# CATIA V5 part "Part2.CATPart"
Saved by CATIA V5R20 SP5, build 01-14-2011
Part number: Part2
Bounding box of the stored display mesh (mm): x -30 to 30, y -75 to 75, z -75 to 75
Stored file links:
  E:\180122237\shuichi\Part2.CATPart
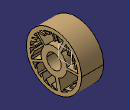
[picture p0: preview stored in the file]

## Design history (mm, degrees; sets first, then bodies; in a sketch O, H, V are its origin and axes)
Body1 (main body)
  Sketch1 on yz-plane, origin (0, 0, 0), H (0, 1, 0), V (0, 0, 1)
    circle A1 centre (0, 0) radius 20
    point P1 (20, 0)
    arc A2 centre (0, 0) radius 35 from (12.1786, -32.8128) to (34.8547, -3.1854) ccw
    arc A3 centre (0, 0) radius 65 from (20, -61.8466) to (38.5836, -52.3097) ccw
    circle A4 centre (0, 0) radius 75
    point P2 (75, 0)
    line L1 (34.8547, -3.1854) -> (64.9219, -3.1854)
    line L2 (34.8547, 3.1854) -> (64.9219, 3.1854)
    point P5 (34.8547, 3.1854)
    point P6 (64.9219, 3.1854)
    line L3 (12.1786, 32.8128) -> (25.6962, 59.7051)
    point P7 (12.1786, 32.8128)
    point P8 (25.6962, 59.7051)
    line L4 (19.068, 29.3498) -> (32.5856, 56.2422)
    point P9 (19.068, 29.3498)
    point P10 (32.5856, 56.2422)
    line L5 (-23.679, 25.7741) -> (-45.3329, 46.5825)
    point P11 (-23.679, 25.7741)
    point P12 (-45.3329, 46.5825)
    line L6 (-27.4563, 21.706) -> (-49.1419, 42.5449)
    point P13 (-27.4563, 21.706)
    point P14 (-49.1419, 42.5449)
    line L7 (-32.8413, -12.1015) -> (-60.0848, -24.7954)
    point P15 (-32.8413, -12.1015)
    point P16 (-60.0848, -24.7954)
    line L8 (-30.3907, -17.361) -> (-57.6342, -30.0549)
    point P17 (-30.3907, -17.361)
    point P18 (-57.6342, -30.0549)
    line L9 (3.1231, -34.8604) -> (9.6221, -64.2839)
    point P20 (9.6221, -64.2839)
    line L10 (12.1786, -32.8128) -> (20, -61.8466)
    arc A5 centre (0, 0) radius 65 from (64.9219, 3.1854) to (60.6959, 23.2596) ccw
    arc A6 centre (0, 0) radius 35 from (34.8547, 3.1854) to (19.068, 29.3498) ccw
    arc A7 centre (0, 0) radius 35 from (12.1786, 32.8128) to (-23.679, 25.7741) ccw
    arc A8 centre (0, 0) radius 65 from (25.6962, 59.7051) to (8.1597, 64.4858) ccw
    arc A9 centre (0, 0) radius 65 from (-49.1419, 42.5449) to (-55.4195, 33.9658) ccw
    arc A10 centre (0, 0) radius 35 from (-27.4563, 21.706) to (-32.8413, -12.1015) ccw
    arc A11 centre (0, 0) radius 35 from (-30.3907, -17.361) to (3.1231, -34.8604) ccw
    arc A12 centre (0, 0) radius 65 from (-57.6342, -30.0549) to (-49.1419, -42.5449) ccw
    point P23 (63.8636, -12.1015)
    line L11 (63.8636, -12.1015) -> (51.2581, -24.2284)
    line L12 (51.2581, -24.2284) -> (52.5418, -26.7943)
    line L13 (52.5418, -26.7943) -> (62.7428, -16.9806)
    point P26 (62.7428, -16.9806)
    point P27 (56.9345, -31.3603)
    line L14 (56.9345, -31.3603) -> (43.0207, -38.3216)
    point P28 (43.0207, -38.3216)
    line L15 (43.0207, -38.3216) -> (43.658, -41.6313)
    line L16 (43.658, -41.6313) -> (53.7174, -36.5984)
    point P30 (53.7174, -36.5984)
    point P31 (44.7238, -47.1676)
    line L17 (44.7238, -47.1676) -> (26.1689, -52.1661)
    point P32 (26.1689, -52.1661)
    line L18 (26.1689, -52.1661) -> (25.6962, -54.7909)
    line L19 (25.6962, -54.7909) -> (38.5836, -52.3097)
    point P35 (9.6221, -64.2839)
    line L20 (9.6221, -64.2839) -> (-6.3464, -56.2572)
    line L21 (-6.3464, -56.2572) -> (-8.0756, -58.0092)
    line L22 (-8.0756, -58.0092) -> (5.3872, -64.7764)
    point P38 (5.3872, -64.7764)
    point P39 (-9.0397, -64.3683)
    line L23 (-9.0397, -64.3683) -> (-21.8516, -52.0566)
    point P40 (-21.8516, -52.0566)
    line L24 (-21.8516, -52.0566) -> (-21.9294, -54.2587)
    line L25 (-21.9294, -54.2587) -> (-12.8253, -63.7222)
    point P42 (-12.8253, -63.7222)
    point P43 (-25.6962, -59.7051)
    line L26 (-25.6962, -59.7051) -> (-32.8413, -44.9408)
    line L27 (-32.8413, -44.9408) -> (-36.2988, -47.1676)
    line L28 (-36.2988, -47.1676) -> (-34.5572, -55.0527)
    point P46 (-34.5572, -55.0527)
    point P47 (-43.0874, -48.667)
    line L29 (-43.0874, -48.667) -> (-47.1347, -30.3431)
    line L30 (-47.1347, -30.3431) -> (-49.1419, -30.7649)
    line L31 (-49.1419, -30.7649) -> (-49.1419, -42.5449)
    point P51 (-61.8425, -20.0127)
    line L32 (-61.8425, -20.0127) -> (-53.2098, -2.8387)
    point P52 (-53.2098, -2.8387)
    line L33 (-53.2098, -2.8387) -> (-56.8424, 0)
    point P53 (-56.8424, 0)
    line L34 (-56.8424, 0) -> (-63.5962, -13.436)
    point P54 (-63.5962, -13.436)
    point P55 (-65, 0)
    line L35 (-65, 0) -> (-48.9784, 10.238)
    point P56 (-48.9784, 10.238)
    line L36 (-48.9784, 10.238) -> (-50.5309, 12.5563)
    point P57 (-50.5309, 12.5563)
    line L37 (-50.5309, 12.5563) -> (-64.8173, 4.8695)
    point P58 (-64.8173, 4.8695)
    point P59 (-62.766, 16.8945)
    line L38 (-62.766, 16.8945) -> (-45.6326, 22.3012)
    point P60 (-45.6326, 22.3012)
    line L39 (-45.6326, 22.3012) -> (-49.1419, 26.3719)
    point P61 (-49.1419, 26.3719)
    line L40 (-49.1419, 26.3719) -> (-60.2974, 24.274)
    point P62 (-60.2974, 24.274)
    point P63 (-58.7447, 27.822)
    line L41 (-58.7447, 27.822) -> (-40.9443, 33.4392)
    line L42 (-40.9443, 33.4392) -> (-49.1419, 35.9468)
    point P65 (-49.1419, 35.9468)
    line L43 (-49.1419, 35.9468) -> (-55.4195, 33.9658)
    line L44 (-45.3329, 46.5825) -> (-25.6989, 46.5825)
    line L45 (-25.6989, 46.5825) -> (-26.2108, 50.8739)
    point P68 (-26.2108, 50.8739)
    line L46 (-26.2108, 50.8739) -> (-40.458, 50.8739)
    point P69 (-40.458, 50.8739)
    point P70 (-33.4355, 55.7411)
    line L47 (-33.4355, 55.7411) -> (-13.2841, 55.7411)
    line L48 (-13.2841, 55.7411) -> (-12.5955, 61.3306)
    line L49 (-12.5955, 61.3306) -> (-28.7617, 58.2904)
    point P73 (-28.7617, 58.2904)
    point P74 (-6.287, 64.6952)
    line L50 (-6.287, 64.6952) -> (1.4725, 46.8245)
    point P75 (1.4725, 46.8245)
    line L51 (1.4725, 46.8245) -> (4.6346, 49.4646)
    line L52 (4.6346, 49.4646) -> (-2.0962, 64.9662)
    point P77 (-2.0962, 64.9662)
    point P78 (5.6215, 64.7565)
    line L53 (5.6215, 64.7565) -> (13.3178, 50.0458)
    point P79 (13.3178, 50.0458)
    line L54 (13.3178, 50.0458) -> (14.6136, 50.8739)
    point P80 (14.6136, 50.8739)
    line L55 (14.6136, 50.8739) -> (8.1597, 64.4858)
    point P82 (33.4355, 55.7411)
    line L56 (33.4355, 55.7411) -> (37.7742, 33.2055)
    line L57 (37.7742, 33.2055) -> (41.5099, 33.0239)
    point P84 (41.5099, 33.0239)
    line L58 (41.5099, 33.0239) -> (37.6694, 52.9718)
    point P85 (37.6694, 52.9718)
    point P86 (45.3329, 46.5825)
    line L59 (45.3329, 46.5825) -> (47.8485, 25.4953)
    point P87 (47.8485, 25.4953)
    line L60 (47.8485, 25.4953) -> (50.4782, 24.9288)
    line L61 (50.4782, 24.9288) -> (50.4782, 40.9506)
    point P89 (50.4782, 40.9506)
    point P90 (57.6342, 30.0549)
    line L62 (57.6342, 30.0549) -> (54.2274, 11.1363)
    point P91 (54.2274, 11.1363)
    line L63 (54.2274, 11.1363) -> (58.1438, 9.0879)
    point P92 (58.1438, 9.0879)
    line L64 (58.1438, 9.0879) -> (60.6959, 23.2596)
    arc A13 centre (0, 0) radius 65 from (44.7238, -47.1676) to (53.7174, -36.5984) ccw
    arc A14 centre (0, 0) radius 65 from (56.9345, -31.3603) to (62.7428, -16.9806) ccw
    arc A15 centre (0, 0) radius 65 from (63.8636, -12.1015) to (64.9219, -3.1854) ccw
    arc A16 centre (0, 0) radius 65 from (57.6342, 30.0549) to (50.4782, 40.9506) ccw
    arc A17 centre (0, 0) radius 65 from (45.3329, 46.5825) to (37.6694, 52.9718) ccw
    arc A18 centre (0, 0) radius 65 from (33.4355, 55.7411) to (32.5856, 56.2422) ccw
    arc A19 centre (0, 0) radius 65 from (5.6215, 64.7565) to (-2.0962, 64.9662) ccw
    arc A20 centre (0, 0) radius 65 from (-6.287, 64.6952) to (-28.7617, 58.2904) ccw
    arc A21 centre (0, 0) radius 65 from (-33.4355, 55.7411) to (-40.458, 50.8739) ccw
    arc A22 centre (0, 0) radius 65 from (-58.7447, 27.822) to (-60.2974, 24.274) ccw
    arc A23 centre (0, 0) radius 65 from (-62.766, 16.8945) to (-64.8173, 4.8695) ccw
    arc A24 centre (0, 0) radius 65 from (-65, 0) to (-63.5962, -13.436) ccw
    arc A25 centre (0, 0) radius 65 from (-61.8425, -20.0127) to (-60.0848, -24.7954) ccw
    arc A26 centre (0, 0) radius 65 from (-43.0874, -48.667) to (-34.5572, -55.0527) ccw
    arc A27 centre (0, 0) radius 65 from (-25.6962, -59.7051) to (-12.8253, -63.7222) ccw
    arc A28 centre (0, 0) radius 65 from (-9.0397, -64.3683) to (5.3872, -64.7764) ccw
    radius A2 = 35
    radius A4 = 75
    radius A3 = 65
    coincidence: A1 P1, P1 H, A4 P2, P2 H, P5 A2, P6 A3, P7 A2, P8 A3, P9 A2, P10 A3, P11 A2, P12 A3, P13 A2, P14 A3, P15 A2, P16 A3, P17 A2, P18 A3, A3 A5, A2 A6, A6 A7, A5 A8, A8 A9, A7 A10, A10 A11, A9 A12, P23 A3, L11 P20, P26 A3, P27 A3, P28 L5, P30 A3, P31 L15, P31 A3, P32 L13, P35 A12, P38 A12, P39 L14, P39 A12, P40 L4, P42 A12, P43 A12, P43 L4, P46 A12, P47 A12, P51 A9, P52 L29, P53 H, P54 A9, P55 A9, P55 H, P56 L28, P57 L34, P58 A9, P59 L26, P59 A9, P60 L34, P61 L31, P62 A9, P63 A9, P65 L31, P68 L32, P69 A8, P70 A8, P73 A8, P74 A8, P75 L41, P77 A8, P78 L49, P78 A8, P79 L35, P80 L46, P82 L47, P82 A5, P84 L18, P85 A5, P86 L44, P86 A5, P87 L7, P89 A5, P90 A5, P90 L7, P91 L27, P92 L21, A3 A13, A13 A14, A14 A15, A5 A16, A16 A17, A17 A18, A8 A19, A19 A20, A20 A21, A9 A22, A22 A23, A23 A24, A24 A25, A12 A26, A26 A27, A27 A28, P20 P35
    horizontal: L1 H, L2 H, L44 H, L46 H, L47 H
    parallelism: L4 L3, L6 L5, L8 L7, L13 L11, L16 L14, L22 L20, L23 L6, L28 L9, L29 L28, L32 L3, L34 L32, L41 L38, L43 L41, L49 L40, L52 L50, L56 L15, L58 L56, L59 L45, L62 L18, L64 L62
    tangency: L12 A2, L15 A2, L18 A2, L21 A2, L24 A1, L27 A1, L30 A1, L33 A2, L35 A2, L36 A2, L37 A2, L38 A2, L39 A1, L40 A2, L42 A1, L45 A1, L48 A1, L50 A1, L51 A2, L53 A2, L54 A2, L55 A2, L57 A2, L60 A2, L63 A2
    perpendicularity: L14 L12, L17 L10, L19 L15, L20 L4, L25 L11
    vertical: L31 V, L61 V
  Pad1: profile Sketch1, direction (1, 0, 0), length 30, mirrored extent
